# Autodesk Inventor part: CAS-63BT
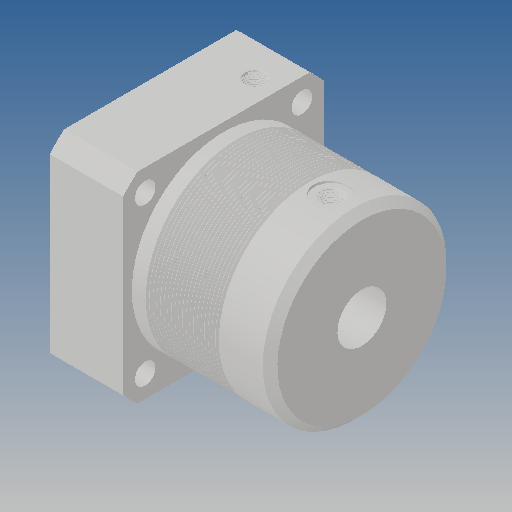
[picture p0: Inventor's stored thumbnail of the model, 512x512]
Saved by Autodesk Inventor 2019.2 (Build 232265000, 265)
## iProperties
Created: 2009-09
Part Number: CAS-63BT
Material: Ogólny
Document SubType Name: Modeling
Designer: CADENGINEERING4
Density: 1 g/cm^3
Appearance: Domyślna
Author: CADENGINEERING4
Revision Number: 1LAST_VERSION
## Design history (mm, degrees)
feature "Baza1"
node "Bryła1"
